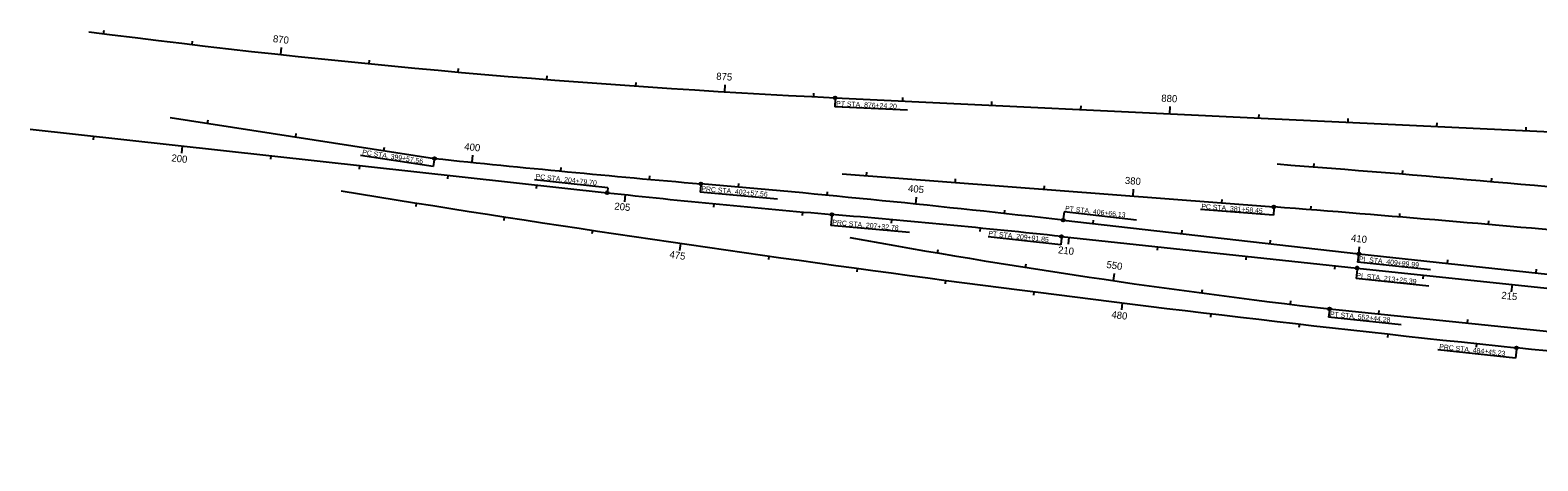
# Model space of a CAD drawing. Extents: x 919451 to 931682, y 583214 to 665619.
# Drawn here: x 925162 to 926854, y 636510 to 636993 of the extents above; entities that cross this region are included whole.
import ezdxf

# ---------------------------------------------------------------- set-up
doc = ezdxf.new("R2010")
doc.units = 0
for name, color, linetype in [('CLConst_dp', 7, 'Continuous'), ('ScratchEle_dp', 7, 'Continuous'), ('StationTicL_dp', 7, 'Continuous'), ('StationTicS_dp', 7, 'Continuous'), ('TextBLStation', 7, 'Continuous')]:
    doc.layers.add(name, color=color, linetype=linetype)

msp = doc.modelspace()

# ---------------------------------------------------------------- linework, layer by layer
at = {"layer": 'CLConst_dp'}
for p, q in [((926065.6, 636917.3), (926567.1, 636893.5)), ((925319.4, 636895.2), (925616, 636849.3)), ((926567.1, 636893.5), (926993.8, 636873.2)), ((925162.4, 636882), (925809.7, 636810.9)), ((926073.4, 636832), (926557.7, 636794.9)), ((926321.2, 636780.1), (926652.9, 636742.2)), ((926319.5, 636761.8), (926651.2, 636726.3)), ((926652.9, 636742.2), (927135.4, 636690.7)), ((926651.2, 636726.3), (927389.3, 636647.6)), ((926620.1, 636680.5), (927084.2, 636633))]:
    msp.add_line(p, q, dxfattribs=at)
for centre, radius, start, end in [((926557.1, 647252.3), 10346.6, 262.62062, 267.27698), ((927324.2, 653175.3), 16415.1, 264.02664, 265.07377), ((924808.6, 613941.4), 22968.3, 83.18963, 85.62345), ((924651.1, 622161.2), 14714, 83.48281, 85.07377), ((929201.8, 659432.1), 22918.3, 260.7334, 264.05982), ((926900.3, 646742.2), 9991, 263.7334, 265.18477), ((925098.5, 625352.9), 11474, 83.8911, 85.18477), ((924808.6, 613941.4), 22920.3, 84.65698, 85.62345), ((927580.5, 644977.1), 8352, 259.66422, 263.3969), ((922957, 599413.8), 37424, 82.41196, 84.05982)]:
    msp.add_arc(centre, radius, start, end, dxfattribs=at)
at = {"layer": 'StationTicL_dp'}
for p, q in [((926065.5, 636915.7), (926065.1, 636907.1)), ((926146.7, 636903.3), (926065.1, 636907.1)), ((925614.4, 636840.1), (925532.9, 636852.7)), ((925615.6, 636847.8), (925614.4, 636840.1)), ((925810.3, 636816.3), (925728.3, 636825.3)), ((925914.6, 636819.2), (925913.9, 636811.5)), ((925810.3, 636816.3), (925809.9, 636812.5)), ((926000.6, 636803.8), (925913.9, 636811.5)), ((926061.6, 636784.8), (926060.6, 636774.2)), ((926322.2, 636789.4), (926321.3, 636781.7)), ((926403.7, 636780), (926322.2, 636789.4)), ((926557.1, 636785.6), (926475.5, 636791.9)), ((926557.7, 636793.3), (926557.1, 636785.6)), ((926148.8, 636766.3), (926060.6, 636774.2)), ((926318.5, 636752.5), (926237, 636761.3)), ((926319.3, 636760.2), (926318.5, 636752.5)), ((926652.5, 636740.7), (926651.6, 636733)), ((926733.2, 636724.3), (926651.6, 636733)), ((926651, 636724.7), (926649.9, 636714.7)), ((926731.5, 636706), (926649.9, 636714.7)), ((926619.9, 636679), (926619, 636671.1)), ((926700.6, 636662.7), (926619, 636671.1)), ((926828.8, 636625.2), (926741.4, 636634.6)), ((926829.8, 636635.3), (926828.8, 636625.2))]:
    msp.add_line(p, q, dxfattribs=at)
for centre in [(926065.6, 636917.3), (925616, 636849.3), (925914.6, 636820.8), (925809.7, 636810.9), (926061.6, 636786.4), (926557.7, 636794.9), (926321.2, 636780.1), (926319.5, 636761.8), (926652.9, 636742.2), (926651.2, 636726.3), (926620.1, 636680.5), (926830, 636636.9)]:
    msp.add_circle(centre, 1.6, dxfattribs=at)
at = {"layer": 'StationTicS_dp'}
for p, q in [((925443.4, 636965.8), (925444.2, 636973.7)), ((925941.6, 636924), (925942.1, 636932)), ((926441, 636899.5), (926441.4, 636907.5)), ((925332.9, 636863.2), (925332, 636855.3)), ((925658.2, 636845), (925659, 636852.9)), ((925829.9, 636808.7), (925829.1, 636800.7)), ((926156, 636798), (926156.8, 636806)), ((926399.7, 636807), (926400.3, 636815)), ((925892.1, 636754), (925891, 636746.1)), ((926327.6, 636760.9), (926326.8, 636753)), ((926652.9, 636742.2), (926653.7, 636750.2)), ((926377.8, 636712.2), (926379, 636720.1)), ((926824.8, 636707.8), (926823.9, 636699.8)), ((926387.6, 636687.2), (926386.6, 636679.3))]:
    msp.add_line(p, q, dxfattribs=at)
at = {"layer": 'TextBLStation'}
for p, q in [((925244.8, 636989.2), (925245.3, 636993.2)), ((925344, 636977), (925344.5, 636981)), ((925542.8, 636955.5), (925543.2, 636959.5)), ((925642.4, 636946.2), (925642.8, 636950.2)), ((925742.1, 636937.8), (925742.4, 636941.8)), ((925841.8, 636930.4), (925842.1, 636934.4)), ((926041.4, 636918.5), (926041.6, 636922.5)), ((926141.3, 636913.7), (926141.5, 636917.7)), ((926241.2, 636909), (926241.4, 636913)), ((926341.1, 636904.2), (926341.3, 636908.2)), ((925361.5, 636888.7), (925362.1, 636892.6)), ((926540.9, 636894.7), (926541.1, 636898.7)), ((926640.8, 636890), (926640.9, 636894)), ((926740.6, 636885.2), (926740.8, 636889.2)), ((926840.5, 636880.5), (926840.7, 636884.5)), ((925233.5, 636874.2), (925233.1, 636870.2)), ((925460.3, 636873.4), (925460.9, 636877.3)), ((925432.3, 636852.3), (925431.9, 636848.4)), ((925559.1, 636858.1), (925559.7, 636862.1)), ((925531.7, 636841.4), (925531.3, 636837.4)), ((925757.7, 636835.1), (925758.1, 636839.1)), ((926100.6, 636829.9), (926100.9, 636833.9)), ((926602.4, 636839.6), (926602.7, 636843.6)), ((926702.1, 636831.6), (926702.4, 636835.6)), ((925631.1, 636830.5), (925630.7, 636826.5)), ((925730.5, 636819.6), (925730.1, 636815.6)), ((925857.3, 636825.9), (925857.7, 636829.9)), ((925956.9, 636817.1), (925957.3, 636821.1)), ((926200.3, 636822.3), (926200.6, 636826.3)), ((926300, 636814.6), (926300.3, 636818.6)), ((926801.7, 636823.1), (926802.1, 636827.1)), ((926056.5, 636807.9), (926056.9, 636811.9)), ((926499.4, 636799.4), (926499.7, 636803.4)), ((925595.5, 636799.3), (925594.9, 636795.3)), ((925694.3, 636783.8), (925693.7, 636779.8)), ((925929.4, 636798.5), (925929, 636794.5)), ((926029, 636789.3), (926028.6, 636785.3)), ((926255.4, 636787.5), (926255.9, 636791.4)), ((926599.1, 636791.7), (926599.4, 636795.7)), ((926698.8, 636783.7), (926699.1, 636787.7)), ((925793.2, 636768.7), (925792.6, 636764.7)), ((926128.6, 636780.6), (926128.2, 636776.6)), ((926228.1, 636771.2), (926227.7, 636767.2)), ((926354.8, 636776.3), (926355.3, 636780.2)), ((926454.2, 636764.9), (926454.6, 636768.9)), ((926798.4, 636775.2), (926798.8, 636779.2)), ((926427, 636750.3), (926426.6, 636746.3)), ((926553.5, 636753.6), (926554, 636757.5)), ((925991.1, 636739.8), (925990.5, 636735.8)), ((926180.3, 636743.3), (926181, 636747.3)), ((926526.5, 636739.6), (926526, 636735.7)), ((926752.3, 636731.6), (926752.7, 636735.6)), ((926090.1, 636726), (926089.6, 636722)), ((926279, 636727.2), (926279.6, 636731.1)), ((926625.9, 636729), (926625.5, 636725)), ((926725.3, 636718.4), (926724.9, 636714.4)), ((926851.7, 636721), (926852.2, 636725)), ((926189.2, 636712.7), (926188.7, 636708.7)), ((926288.4, 636699.7), (926287.9, 636695.8)), ((926476.9, 636698.4), (926477.4, 636702.3)), ((926576.1, 636685.8), (926576.6, 636689.7)), ((926486.9, 636675.2), (926486.4, 636671.2)), ((926675.5, 636674.9), (926675.9, 636678.8)), ((926775, 636664.7), (926775.4, 636668.6)), ((926586.2, 636663.5), (926585.8, 636659.6)), ((926685.6, 636652.3), (926685.1, 636648.4)), ((926785, 636641.6), (926784.6, 636637.6))]:
    msp.add_line(p, q, dxfattribs=at)

# ---------------------------------------------------------------- texts
at = {"layer": 'ScratchEle_dp'}
for s, rotation, p in [('870', 353.8204, (925434.4, 636979.8)), ('875', 356.5892, (925931.9, 636937.6)), ('880', 357.277, (926431.2, 636913)), ('200', 353.7334, (925320.5, 636846.1)), ('400', 354.1748, (925649.1, 636858.9)), ('405', 354.1297, (926146.9, 636812)), ('380', 355.6234, (926390.3, 636820.8)), ('205', 354.3989, (925817.5, 636792)), ('210', 353.8911, (926315.2, 636742.9)), ('410', 353.9111, (926643.9, 636756.2)), ('475', 351.6968, (925879.2, 636738)), ('550', 351.7211, (926369.4, 636726.6)), ('215', 353.9111, (926812.5, 636692)), ('480', 352.9468, (926375, 636670.5))]:
    msp.add_text(s, height=8, rotation=rotation, dxfattribs=at).set_placement(p)
at = {"layer": 'StationTicL_dp'}
for s, rotation, p in [('PT STA. 876+24.20', 357.277, (926066.5, 636908.2)), ('PC STA. 399+57.56', 351.2117, (925534.6, 636853.8)), ('PC STA. 204+79.70', 353.7334, (925729.2, 636826.5)), ('PRC STA. 402+57.56', 354.9002, (925915.2, 636812.8)), ('PT STA. 406+66.13', 353.4828, (926323.2, 636790.7)), ('PC STA. 381+58.45', 355.6234, (926476.1, 636792.9)), ('PRC STA. 207+32.78', 354.9002, (926062.1, 636775.1)), ('PT STA. 209+91.85', 353.8911, (926237.1, 636762.6)), ('PI  STA. 409+99.99', 353.8911, (926652.8, 636734.1)), ('PI  STA. 213+25.39', 353.8911, (926650, 636715.5)), ('PT STA. 552+44.28', 354.1462, (926620.3, 636672.2)), ('PRC STA. 484+45.23', 353.8911, (926742.9, 636635.6))]:
    msp.add_text(s, height=5.6, rotation=rotation, dxfattribs=at).set_placement(p)

doc.saveas('drawing.dxf')
